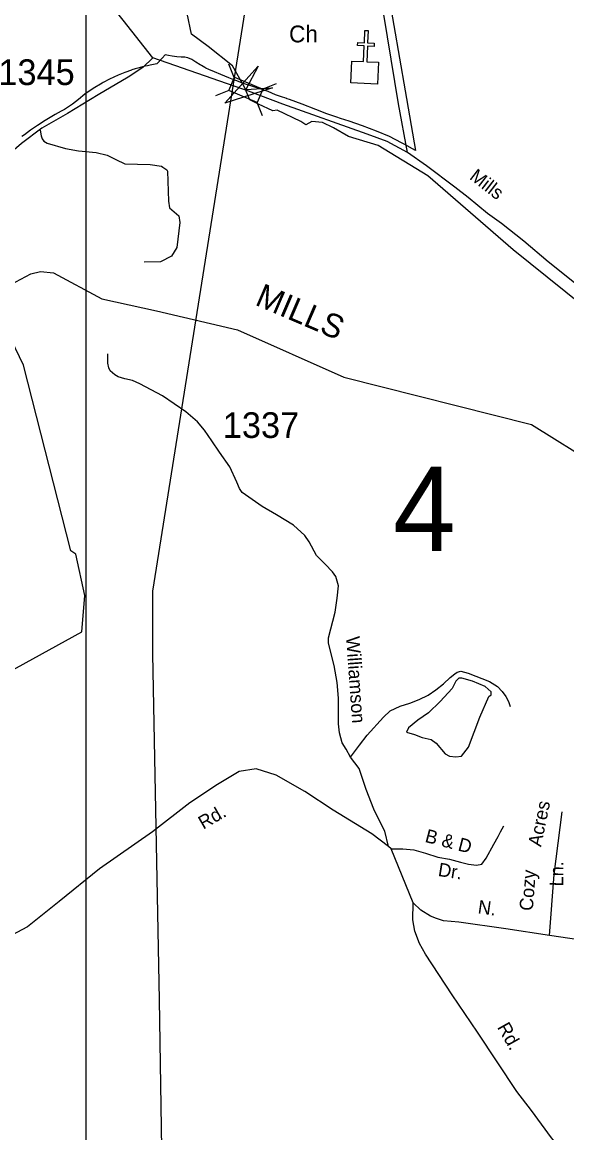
# Model space of a CAD drawing. Extents: x 884530 to 1028605, y 526725 to 653634.
# Drawn here: x 928710 to 931362, y 615382 to 620795 of the extents above; entities that cross this region are included whole.
import ezdxf

# ---------------------------------------------------------------- set-up
doc = ezdxf.new("R2010")
doc.units = 0
for name, color, linetype in [('Exist Boundary Political City Limit New', 7, 'Continuous'), ('Exist Cultural Church CELL', 7, 'Continuous'), ('Exist Cultural Church Label', 7, 'Continuous'), ('Exist Hydrographic Creek Single Shore', 7, 'Continuous'), ('Exist Hydrographic Pond Over 1500 Sq Ft', 7, 'Continuous'), ('Exist Hydrographic River Shore', 7, 'Continuous'), ('Exist Hydrographic River Shore Label', 7, 'Continuous'), ('Exist Road Non-System Type 51', 7, 'Continuous'), ('Exist Road Non-System Type 51 Label', 7, 'Continuous'), ('Exist Road Secondary Structure Standard Bridge Attributed CELL', 7, 'Continuous'), ('Exist Road Secondary Structure Standard Bridge CELL', 7, 'Continuous'), ('Exist Road Secondary Structure Standard Bridge Number Label', 7, 'Continuous'), ('Exist Road Secondary Type 41 Attributed', 7, 'Continuous'), ('Exist Road Secondary Type 51 Attributed', 7, 'Continuous'), ('Exist Road Secondary Type 51 Label', 7, 'Continuous'), ('Exist Road Secondary Type 51 Number Label', 7, 'Continuous'), ('Exist Utilities Electrical Transmission Line', 7, 'Continuous'), ('Map Preparation Boundary City Limit Buffer Line', 7, 'Continuous'), ('Map Preparation Inset Cut Line', 7, 'Continuous')]:
    doc.layers.add(name, color=color, linetype=linetype)

msp = doc.modelspace()

# ---------------------------------------------------------------- linework, layer by layer
at = {"layer": 'Exist Boundary Political City Limit New'}
for points in [[(930491.6, 620940.2), (930574.2, 620461), (930624.4, 620169.5), (930569.2, 620200.9), (930556.8, 620207.9), (930498.7, 620237.3), (930434.4, 620264.7), (930366.3, 620290.1), (930302, 620312.2), (930259.6, 620326.4), (930242, 620332.2), (930193.1, 620349.2), (930139.1, 620369.8), (930073.5, 620395.2), (930072.6, 620395.6), (930011.1, 620418.6), (930000, 620422.3), (929998.6, 620422.8), (929997.1, 620423.2), (929989, 620425.9), (929978, 620429.6), (929943.4, 620440.4), (929907.4, 620457.2), (929882.3, 620465.8), (929823, 620485.8), (929797.6, 620493.8), (929778.9, 620500.1), (929750.1, 620510.9), (929739.5, 620515), (929715.2, 620524.5), (929677.6, 620539.7), (929646.4, 620552.8), (929618.1, 620564.8), (929604.2, 620571.7), (929599.6, 620574.1), (929590.1, 620579.1), (929582.7, 620583.5), (929575.9, 620587.4), (929555.2, 620601), (929535, 620613.7), (929516.3, 620621.8), (929514.4, 620622.1), (929501.7, 620624.1), (929484.3, 620625.1), (929462.4, 620627), (929439.7, 620630.1), (929421.8, 620633.1), (929406.4, 620635.8), (929391.7, 620620.5), (929364.8, 620592.6), (929333.4, 620586.4), (929319, 620583.3), (929306.9, 620580.7), (929302.5, 620579.7), (929272.5, 620571.9), (929259.4, 620567.6)], [(929259.4, 620567.6), (929243.3, 620562.4), (929241.2, 620561.7), (929209.9, 620549.8), (929176.6, 620536.3), (929135.4, 620518.2), (929103.6, 620501.4), (929098.3, 620498.6), (929054.6, 620472.3), (929014.6, 620444.7), (928983, 620419.2), (928953.9, 620396), (928914.7, 620370.4), (928899.6, 620361.8), (928870.5, 620345.1), (928822, 620316.4), (928783.6, 620291.9), (928750.2, 620268.8), (928719.9, 620246.8), (928708.4, 620238.5)]]:
    msp.add_lwpolyline(points, dxfattribs=at)
at = {"layer": 'Exist Cultural Church CELL'}
msp.add_lwpolyline([(930314.9, 620605.7), (930371.8, 620603.2), (930375.3, 620679.3), (930343.3, 620680.8), (930344, 620696.7), (930376, 620695.3), (930378.7, 620755.3), (930394.8, 620754.6), (930392, 620694.5), (930424, 620693.1), (930423.2, 620677.1), (930391.3, 620678.6), (930387.8, 620602.5), (930445.4, 620599.8), (930440.5, 620493.4), (930310, 620499.4)], close=True, dxfattribs=at)
at = {"layer": 'Exist Hydrographic Creek Single Shore'}
for points in [[(929790, 620481.1), (929733, 620582.2), (929614.5, 620677.1), (929534.5, 620736.4), (929513.7, 620837.2), (929548.1, 621026.1)], [(932621.2, 618595.1), (932462.2, 618668.5), (932455, 618790.8), (932311.3, 618956.2), (932061.5, 619033), (931806.9, 619143.1), (931522.4, 619345.7), (931100.9, 619685.5), (930685.5, 620047), (930442.7, 620194.3), (930299.3, 620237.9), (930226.1, 620280.1), (930171.3, 620306.8), (930120.7, 620311.1), (930091.2, 620295.6), (930067.3, 620311.1), (929951.3, 620366.6), (929930.2, 620363.8), (929860.4, 620395.5), (929818.9, 620416.2), (929790, 620481.1)]]:
    msp.add_lwpolyline(points, dxfattribs=at)
at = {"layer": 'Exist Hydrographic Pond Over 1500 Sq Ft'}
msp.add_lwpolyline([(930821.9, 617214), (930849.8, 617217.9), (930883.1, 617261.9), (930937.6, 617408.2), (930981.5, 617508), (930993.4, 617517.3), (930993.4, 617531.9), (930964.2, 617557.2), (930903, 617583.8), (930851.2, 617598.4), (930836.5, 617598.4), (930821.9, 617583.8), (930803.3, 617547.9), (930744.8, 617484), (930688.9, 617429.5), (930635.8, 617393.6), (930590.6, 617356.3), (930581.2, 617335), (930619.8, 617323), (930657, 617309.7), (930700.9, 617299.1), (930726.2, 617280.5), (930770, 617228.6), (930791.3, 617217.9)], close=True, dxfattribs=at)
at = {"layer": 'Exist Hydrographic River Shore'}
for points in [[(928629.6, 619504), (928751.8, 619568.7), (928799, 619579.5), (928862, 619573), (929096.9, 619446.5), (929364.1, 619389), (929758.3, 619295.4), (930275.8, 619065.3), (931189.8, 618834), (931513.3, 618632.6)], [(928600.9, 617605.2), (928999.4, 617824.4), (929014.1, 618001.3), (928971.3, 618202.4), (928946.9, 618219.2), (928715.9, 619122.8), (928593.7, 619374.5)]]:
    msp.add_lwpolyline(points, dxfattribs=at)
at = {"layer": 'Exist Road Non-System Type 51'}
for points in [[(928796.3, 620268.9), (928802.5, 620241.6), (928806.1, 620226.1), (928815.1, 620215.3), (928831.1, 620205.6), (928920.9, 620179.1), (928984.4, 620168), (929070.4, 620160.9), (929122.9, 620146.4), (929165.4, 620126.6), (929209.2, 620105), (929332.8, 620101.4), (929387.4, 620094), (929394.4, 620089.4), (929414.7, 620075.2), (929417.3, 620069), (929422.1, 619922.9), (929427.2, 619890.7), (929471.8, 619851), (929476.7, 619818.8), (929461.8, 619697.2), (929437, 619655.1), (929382.5, 619627.8), (929303.1, 619625.4)], [(929507, 618896.9), (929393.3, 618974.7), (929282.9, 619032.6), (929246, 619049.5), (929209.5, 619056.8), (929176.2, 619066.1), (929160.3, 619076.8), (929137.7, 619095.4), (929131, 619110), (929127, 619133.3), (929127, 619179.2)], [(930309, 617213), (930351.6, 617271.5), (930388.9, 617320.6), (930468.6, 617407.2), (930500.9, 617438.4), (930550.1, 617462.4), (930597.3, 617476.4), (930643.6, 617493.4), (930685.9, 617515.5), (930724.5, 617541), (930761.4, 617570), (930793.5, 617600.9), (930815.8, 617619.1), (930828.6, 617627.9), (930845.4, 617632.9), (930881.5, 617622.9), (930985.4, 617581.5), (931023.9, 617557.6), (931046.7, 617533.1), (931065.4, 617509.1), (931078.7, 617483.6), (931085.7, 617460)], [(931276.9, 616343.6), (931300.1, 616640.5), (931339.9, 616946.4)], [(930506.2, 616765.5), (930562.5, 616766), (930617, 616761.6), (930674.4, 616745.8), (930733.4, 616726.1), (930790.1, 616715.3), (930843.8, 616701.9), (930882.8, 616691.6), (930921.8, 616687.3), (930948.8, 616692.2), (930968.9, 616720.7), (931006.2, 616789.6), (931027.6, 616826.5), (931039.6, 616849.9), (931055.3, 616877.8)]]:
    msp.add_lwpolyline(points, dxfattribs=at)
at = {"layer": 'Exist Road Secondary Structure Standard Bridge Attributed CELL'}
msp.add_lwpolyline([(929927.8, 620475.4), (929695.8, 620400.4), (929859.2, 620581.3), (929798.2, 620466.6)], close=True, dxfattribs=at)
at = {"layer": 'Exist Road Secondary Structure Standard Bridge CELL'}
for p, q in [((929742.4, 620526.4), (929716.5, 620590.4)), ((929946, 620494.4), (929882, 620468.5)), ((929715.4, 620462.9), (929651.5, 620437)), ((929880.3, 620339.6), (929854.4, 620403.5))]:
    msp.add_line(p, q, dxfattribs=at)
msp.add_lwpolyline([(929854.4, 620403.5), (929715.3, 620462.6), (929742.9, 620527.6), (929882, 620468.5)], close=True, dxfattribs=at)
at = {"layer": 'Exist Road Secondary Type 41 Attributed'}
msp.add_lwpolyline([(929345.2, 620622.2), (929201.2, 620804.6), (929053.1, 620991.8), (929007.9, 621060.2)], dxfattribs=at)
at = {"layer": 'Exist Road Secondary Type 51 Attributed'}
for points in [[(930585.4, 620159.8), (930542, 620397.5), (930470.1, 620832.4)], [(929345.2, 620622.2), (929296.7, 620573.6), (929225.1, 620527.3), (929079.5, 620441.2), (928929.8, 620350.1), (928805.7, 620278.1), (928706.6, 620204.7), (928609.5, 620121.4), (928545.2, 620049.8), (928506.6, 620002.6), (928460.2, 619963.2), (928415.2, 619943.5), (928337.8, 619909.8), (928209.9, 619852.1), (928144.5, 619809.2), (928058.7, 619747.3), (927999.7, 619693.8), (927888.6, 619589.7), (927816.4, 619529.9), (927719.5, 619438.4), (927626.4, 619354.1), (927579.3, 619322.4), (927529.4, 619293.6)], [(929811.4, 620459.4), (929779.6, 620469.9), (929345.2, 620622.2)], [(930585.4, 620159.8), (930486.2, 620213.1), (930389.2, 620249.2), (929978.7, 620395.5), (929811.4, 620459.4)], [(931423.5, 619505), (931271.7, 619626.8), (931152, 619727.7), (931044.3, 619813.3), (930974.9, 619863.5), (930881.4, 619941.1), (930816.7, 619991.7), (930678.2, 620095.1), (930585.4, 620159.8)], [(930494.2, 616778.3), (930475.8, 616852.3), (930450, 616903), (930422, 616959.5), (930385.5, 617056), (930350.9, 617157.8), (930329.3, 617185.4), (930309, 617213), (930288.1, 617251.9), (930268.1, 617283.1), (930255.5, 617331), (930249.5, 617374.9), (930250.2, 617501.3), (930242.9, 617576.5), (930228.2, 617659.6), (930201, 617768.7), (930201, 617795.3), (930234.4, 617919.7), (930243.2, 617988.6), (930249.2, 618048.4), (930236.2, 618094), (930220.9, 618115.9), (930184.3, 618153.1), (930143.5, 618196.1), (930107.6, 618262.6), (930085.7, 618293.2), (930031.3, 618343.8), (929947.7, 618394), (929878.2, 618434.9), (929780.8, 618502.4), (929768.2, 618522.4), (929754.3, 618552.9), (929720.3, 618628.8), (929671.2, 618700), (929633.6, 618754.2), (929597, 618807.4), (929562.5, 618848), (929507, 618896.9)], [(930494.2, 616778.3), (930411.9, 616839.6), (930224.6, 616954.2), (930086, 617045), (929945.9, 617125.4), (929849.7, 617155.5), (929765.6, 617143.5), (929660.4, 617080.3), (929525.1, 616990), (929344.7, 616848.6), (929086.2, 616668.1), (928889.1, 616509.2), (928735.8, 616385.8), (928609.6, 616319.7), (928390.1, 616268.5), (928194.7, 616226.4), (927837, 616196.3)], [(930614.2, 616503.9), (930506.2, 616765.5), (930494.2, 616778.3)], [(932003.6, 616690.1), (931962, 616643.5), (931802.8, 616470.6), (931750.3, 616412.8), (931689.1, 616358.2), (931659.9, 616331.6), (931612, 616314.3), (931564.1, 616306.3), (931476.4, 616314.3), (931276.9, 616343.6), (931064.9, 616376.2), (930836.2, 616408.4), (930761.7, 616416.1), (930727.2, 616426.7), (930697.9, 616437.4), (930651.4, 616466.6), (930614.2, 616503.9)], [(931731.7, 614788.3), (931644.3, 614888.2), (931493.4, 615090.4), (931335.6, 615299.3), (931287, 615357.8), (931189.4, 615490.7), (931119, 615583.8), (930927.7, 615872.6), (930804, 616054.3), (930673.9, 616252.1), (930644.4, 616304.4), (930621.7, 616364.6), (930612.6, 616420.2), (930614.2, 616503.9)]]:
    msp.add_lwpolyline(points, dxfattribs=at)
at = {"layer": 'Exist Utilities Electrical Transmission Line'}
msp.add_lwpolyline([(919215.5, 597808.3), (921124.3, 600075), (921355.3, 603059.1), (925357.2, 607735.8), (926768.3, 610919.4), (927159.2, 611823.9), (928300.4, 613120.2), (929404.2, 614372.6), (929377.4, 616031), (929346.3, 617714.4), (929345.2, 618021.6), (929852.2, 621210.3), (929810.4, 621334.5), (929197.7, 622629.2), (928034.6, 624800), (927482.4, 626024.4), (927504.2, 627587.8), (927629.3, 629272), (927654.5, 630965.2), (927677.4, 631260.1), (927996.2, 631739.4), (928303.4, 632200.5), (928506, 632490), (928981.9, 633140.2)], dxfattribs=at)
at = {"layer": 'Map Preparation Boundary City Limit Buffer Line'}
for points in [[(930491.6, 620940.2), (930574.2, 620461), (930624.4, 620169.5), (930569.2, 620200.9), (930556.8, 620207.9), (930498.7, 620237.3), (930434.4, 620264.7), (930366.3, 620290.1), (930302, 620312.2), (930259.6, 620326.4), (930242, 620332.2), (930193.1, 620349.2), (930139.1, 620369.8), (930073.5, 620395.2), (930072.6, 620395.6), (930011.1, 620418.6), (930000, 620422.3), (929998.6, 620422.8), (929997.1, 620423.2), (929989, 620425.9), (929978, 620429.6), (929943.4, 620440.4), (929907.4, 620457.2), (929882.3, 620465.8), (929823, 620485.8), (929797.6, 620493.8), (929778.9, 620500.1), (929750.1, 620510.9), (929739.5, 620515), (929715.2, 620524.5), (929677.6, 620539.7), (929646.4, 620552.8), (929618.1, 620564.8), (929604.2, 620571.7), (929599.6, 620574.1), (929590.1, 620579.1), (929582.7, 620583.5), (929575.9, 620587.4), (929555.2, 620601), (929535, 620613.7), (929516.3, 620621.8), (929514.4, 620622.1), (929501.7, 620624.1), (929484.3, 620625.1), (929462.4, 620627), (929439.7, 620630.1), (929421.8, 620633.1), (929406.4, 620635.8), (929391.7, 620620.5), (929364.8, 620592.6), (929333.4, 620586.4), (929319, 620583.3), (929306.9, 620580.7), (929302.5, 620579.7), (929272.5, 620571.9), (929259.4, 620567.6)], [(929259.4, 620567.6), (929243.3, 620562.4), (929241.2, 620561.7), (929209.9, 620549.8), (929176.6, 620536.3), (929135.4, 620518.2), (929103.6, 620501.4), (929098.3, 620498.6), (929054.6, 620472.3), (929014.6, 620444.7), (928983, 620419.2), (928953.9, 620396), (928914.7, 620370.4), (928899.6, 620361.8), (928870.5, 620345.1), (928822, 620316.4), (928783.6, 620291.9), (928750.2, 620268.8), (928719.9, 620246.8), (928708.4, 620238.5)]]:
    msp.add_lwpolyline(points, dxfattribs=at)
at = {"layer": 'Map Preparation Inset Cut Line'}
msp.add_lwpolyline([(929019.7, 608590.9), (973281.3, 608590.9), (973281.3, 635645.7), (929019.7, 635645.7)], close=True, dxfattribs=at)

# ---------------------------------------------------------------- texts
at = {"layer": 'Exist Cultural Church Label'}
msp.add_text('Ch', height=82.02, dxfattribs=at).set_placement((930009.2, 620696.8))
at = {"layer": 'Exist Hydrographic River Shore Label'}
msp.add_text('MILLS', height=114.83, rotation=336.7905, dxfattribs=at).set_placement((929838.3, 619419.3))
msp.add_text('MILLS', height=114.83, rotation=336.7905, dxfattribs=at).set_placement((929838.3, 619419.3))
at = {"layer": 'Exist Road Non-System Type 51 Label'}
for s, rotation, p in [('Acres', 78.3779, (931236.4, 616773.5)), ('B & D ', 345.4654, (930667.3, 616800.6)), ('Dr.', 351.0694, (930731.8, 616634.6)), ('Ln.', 89.3944, (931344.2, 616583.2)), ('Cozy', 85.5995, (931196.1, 616462.2))]:
    msp.add_text(s, height=65.62, rotation=rotation, dxfattribs=at).set_placement(p)
at = {"layer": 'Exist Road Secondary Structure Standard Bridge Number Label'}
msp.add_text('4', height=410.1, dxfattribs=at).set_placement((930515.3, 618218.3))
at = {"layer": 'Exist Road Secondary Type 51 Label'}
for s, rotation, p in [('Mills', 322.2439, (930883.8, 620033.6)), ('Williamson', 274.0442, (930286.7, 617799.5)), ('Rd.', 30.1136, (929591.4, 616859.3)), ('N.', 351.8491, (930925.8, 616452.6)), ('Rd.', 299.4089, (931021.1, 615897.2))]:
    msp.add_text(s, height=65.62, rotation=rotation, dxfattribs=at).set_placement(p)
at = {"layer": 'Exist Road Secondary Type 51 Number Label'}
for s, p in [('1345', (928593.3, 620489)), ('1337', (929686.6, 618768.9))]:
    msp.add_text(s, height=125, dxfattribs=at).set_placement(p)

doc.saveas('drawing.dxf')
